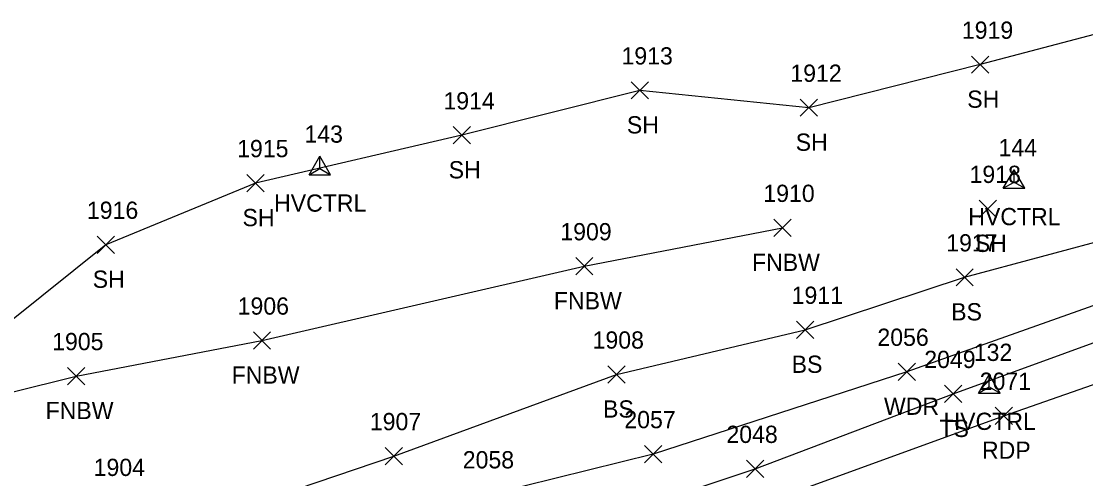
# Model space of a CAD drawing. Extents: x 1526508 to 1531550, y 369926 to 373082.
# Drawn here: x 1531334.3 to 1531457.6, y 370269.7 to 370322.8 of the extents above; entities that cross this region are included whole.
import ezdxf

# ---------------------------------------------------------------- set-up
doc = ezdxf.new("R2010")
doc.units = 0
for name, color, linetype in [('C_A', 7, 'Continuous'), ('C_I', 7, 'Continuous'), ('CPSM', 7, 'Continuous'), ('L_A', 7, 'Continuous'), ('L_I', 7, 'Continuous'), ('L_TIC', 7, 'Continuous'), ('LAWA', 7, 'Continuous'), ('LELB', 7, 'Continuous'), ('LFNC', 7, 'Continuous'), ('LSOGP', 7, 'Continuous'), ('P_A', 7, 'Continuous'), ('P_I', 7, 'Continuous'), ('P_TIC', 7, 'Continuous'), ('PET', 7, 'Continuous'), ('U_I', 7, 'Continuous')]:
    doc.layers.add(name, color=color, linetype=linetype)

msp = doc.modelspace()

# ---------------------------------------------------------------- linework, layer by layer
at = {"layer": 'CPSM'}
for p, q in [((1531367.61, 370304.99), (1531368.86, 370307.15)), ((1531370.11, 370304.99), (1531368.86, 370307.15)), ((1531368.86, 370305.71), (1531368.86, 370307.15)), ((1531367.61, 370304.99), (1531368.86, 370305.71)), ((1531367.61, 370304.99), (1531370.11, 370304.99)), ((1531368.86, 370305.71), (1531368.86, 370305.71)), ((1531368.86, 370305.71), (1531370.11, 370304.99)), ((1531448.07, 370303.42), (1531449.32, 370305.58)), ((1531450.57, 370303.42), (1531449.32, 370305.58)), ((1531449.32, 370304.14), (1531449.32, 370305.58)), ((1531448.07, 370303.42), (1531449.32, 370304.14)), ((1531448.07, 370303.42), (1531450.57, 370303.42)), ((1531449.32, 370304.14), (1531449.32, 370304.14)), ((1531449.32, 370304.14), (1531450.57, 370303.42)), ((1531445.19, 370279.67), (1531446.44, 370281.84)), ((1531447.69, 370279.67), (1531446.44, 370281.84)), ((1531446.45, 370280.4), (1531446.44, 370281.84)), ((1531445.19, 370279.67), (1531446.45, 370280.4)), ((1531446.45, 370280.4), (1531446.45, 370280.4)), ((1531446.45, 370280.4), (1531447.69, 370279.67)), ((1531445.19, 370279.67), (1531447.69, 370279.67))]:
    msp.add_line(p, q, dxfattribs=at)
at = {"layer": 'L_TIC'}
for points in [[(1531444.4, 370316.76), (1531446.4, 370318.76)], [(1531446.4, 370316.76), (1531444.4, 370318.76)], [(1531404.95, 370313.78), (1531406.95, 370315.78)], [(1531406.95, 370313.78), (1531404.95, 370315.78)], [(1531424.52, 370311.77), (1531426.52, 370313.77)], [(1531426.52, 370311.77), (1531424.52, 370313.77)], [(1531384.3, 370308.57), (1531386.3, 370310.57)], [(1531386.3, 370308.57), (1531384.3, 370310.57)], [(1531360.4, 370303.03), (1531362.4, 370305.03)], [(1531362.4, 370303.03), (1531360.4, 370305.03)], [(1531445.28, 370300.04), (1531447.28, 370302.04)], [(1531447.28, 370300.04), (1531445.28, 370302.04)], [(1531421.47, 370297.84), (1531423.47, 370299.84)], [(1531423.47, 370297.84), (1531421.47, 370299.84)], [(1531343.04, 370295.88), (1531345.04, 370297.88)], [(1531345.04, 370295.88), (1531343.04, 370297.88)], [(1531398.51, 370293.39), (1531400.51, 370295.39)], [(1531400.51, 370293.39), (1531398.51, 370295.39)], [(1531442.59, 370292.1), (1531444.59, 370294.1)], [(1531444.59, 370292.1), (1531442.59, 370294.1)], [(1531424.1, 370286.02), (1531426.1, 370288.02)], [(1531426.1, 370286.02), (1531424.1, 370288.02)], [(1531361.15, 370284.77), (1531363.15, 370286.77)], [(1531363.15, 370284.77), (1531361.15, 370286.77)], [(1531339.6, 370280.65), (1531341.6, 370282.65)], [(1531341.6, 370280.65), (1531339.6, 370282.65)], [(1531402.24, 370280.83), (1531404.24, 370282.83)], [(1531404.24, 370280.83), (1531402.24, 370282.83)], [(1531435.88, 370281.15), (1531437.88, 370283.15)], [(1531437.88, 370281.15), (1531435.88, 370283.15)], [(1531441.26, 370278.58), (1531443.26, 370280.58)], [(1531443.26, 370278.58), (1531441.26, 370280.58)], [(1531376.42, 370271.37), (1531378.42, 370273.37)], [(1531378.42, 370271.37), (1531376.42, 370273.37)], [(1531406.49, 370271.6), (1531408.49, 370273.6)], [(1531408.49, 370271.6), (1531406.49, 370273.6)], [(1531418.32, 370269.89), (1531420.32, 370271.89)], [(1531420.32, 370269.89), (1531418.32, 370271.89)]]:
    msp.add_lwpolyline(points, dxfattribs=at)
at = {"layer": 'LAWA'}
msp.add_lwpolyline([(1531521.76, 370311.94), (1531496.07, 370304.92), (1531465.75, 370292.39), (1531436.88, 370282.15), (1531407.49, 370272.6), (1531388.76, 370267.94), (1531371.46, 370261.74), (1531353.51, 370253.07)], dxfattribs=at)
at = {"layer": 'LELB'}
for points in [[(1531144.65, 370206.06), (1531164.57, 370210.72), (1531180.3, 370218.31), (1531196.61, 370223.05), (1531216.18, 370227.2), (1531246.26, 370234.32), (1531259.5, 370237.9), (1531291.92, 370247.44), (1531321.67, 370253.97), (1531341.88, 370260.29), (1531377.42, 370272.37), (1531403.24, 370281.83), (1531425.1, 370287.02), (1531443.59, 370293.1), (1531470.33, 370300.31), (1531494.61, 370309.28), (1531517.9, 370316.82)], [(1531363.93, 370252.47), (1531390.95, 370261.46), (1531419.32, 370270.89), (1531442.26, 370279.58), (1531461.87, 370286.72), (1531494.43, 370297.22), (1531521.4, 370307.47)]]:
    msp.add_lwpolyline(points, dxfattribs=at)
at = {"layer": 'LFNC'}
msp.add_lwpolyline([(1531134.08, 370228.63), (1531150.19, 370233.69), (1531175.89, 370240.05), (1531199.88, 370245.87), (1531222.28, 370250.96), (1531238.05, 370255.18), (1531253.57, 370259.14), (1531283.27, 370267), (1531318.04, 370276.03), (1531340.6, 370281.65), (1531362.15, 370285.77), (1531399.51, 370294.39), (1531422.47, 370298.84)], dxfattribs=at)
at = {"layer": 'LSOGP'}
msp.add_lwpolyline([(1531462.26, 370322.24), (1531445.4, 370317.76), (1531425.52, 370312.77), (1531405.95, 370314.78), (1531385.3, 370309.57), (1531361.4, 370304.03), (1531344.04, 370296.88), (1531318.04, 370276.03)], dxfattribs=at)
at = {"layer": 'P_TIC'}
for points in [[(1531447.12, 370276.05), (1531449.12, 370278.05)], [(1531449.12, 370276.05), (1531447.12, 370278.05)]]:
    msp.add_lwpolyline(points, dxfattribs=at)
at = {"layer": 'PET'}
msp.add_lwpolyline([(1531036.19, 370150.91), (1531061.97, 370155.43), (1531104.8, 370164.58), (1531143.1, 370174.02), (1531180.11, 370184.91), (1531218.48, 370196.81), (1531260.06, 370210.9), (1531302.03, 370225.36), (1531352.57, 370243.2), (1531401.62, 370260.1), (1531448.12, 370277.05), (1531486.93, 370290.59), (1531531.91, 370306.21)], dxfattribs=at)

# ---------------------------------------------------------------- texts
at = {"layer": 'C_A'}
for p in [(1531363.55, 370300.71), (1531444.01, 370299.14), (1531441.14, 370275.4)]:
    msp.add_text('HVCTRL', height=2, dxfattribs=at).set_placement(p)
at = {"layer": 'C_I'}
for s, p in [('143', (1531367.07, 370308.71)), ('144', (1531447.52, 370307.14)), ('132', (1531444.65, 370283.4))]:
    msp.add_text(s, height=2, dxfattribs=at).set_placement(p)
at = {"layer": 'L_A'}
for s, p in [('SH', (1531443.89, 370312.76)), ('SH', (1531404.44, 370309.78)), ('SH', (1531424.01, 370307.77)), ('SH', (1531383.79, 370304.57)), ('SH', (1531359.89, 370299.03)), ('SH', (1531444.77, 370296.04)), ('FNBW', (1531418.94, 370293.84)), ('SH', (1531342.53, 370291.88)), ('FNBW', (1531395.98, 370289.39)), ('BS', (1531442.03, 370288.1)), ('BS', (1531423.54, 370282.02)), ('FNBW', (1531358.63, 370280.77)), ('FNBW', (1531337.07, 370276.65)), ('BS', (1531401.68, 370276.83)), ('WDR', (1531434.24, 370277.15)), ('TS', (1531440.67, 370274.58))]:
    msp.add_text(s, height=2, dxfattribs=at).set_placement(p)
at = {"layer": 'L_I'}
for s, p in [('1919', (1531443.27, 370320.76)), ('1913', (1531403.82, 370317.78)), ('1912', (1531423.39, 370315.77)), ('1914', (1531383.18, 370312.57)), ('1915', (1531359.27, 370307.03)), ('1918', (1531444.16, 370304.04)), ('1910', (1531420.26, 370301.84)), ('1916', (1531341.86, 370299.88)), ('1909', (1531396.73, 370297.39)), ('1917', (1531441.46, 370296.1)), ('1911', (1531423.54, 370290.02)), ('1906', (1531359.33, 370288.77)), ('1905', (1531337.83, 370284.65)), ('1908', (1531400.47, 370284.83)), ('2056', (1531433.48, 370285.15)), ('2049', (1531438.91, 370282.58)), ('1907', (1531374.65, 370275.37)), ('2057', (1531404.15, 370275.6)), ('2048', (1531415.98, 370273.89)), ('2058', (1531385.42, 370270.94))]:
    msp.add_text(s, height=2, dxfattribs=at).set_placement(p)
at = {"layer": 'P_A'}
msp.add_text('RDP', height=2, dxfattribs=at).set_placement((1531445.6, 370272.05))
at = {"layer": 'P_I'}
msp.add_text('2071', height=2, dxfattribs=at).set_placement((1531445.34, 370280.05))
at = {"layer": 'U_I'}
msp.add_text('1904', height=2, dxfattribs=at).set_placement((1531342.64, 370270.06))

doc.saveas('drawing.dxf')
